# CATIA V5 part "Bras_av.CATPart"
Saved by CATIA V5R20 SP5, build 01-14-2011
Part number: Skl_Bras_av
Publications: "Axe_glissiere_bras_av/vol_av", "Axe_pivot_bras_av/pignon_av", "Plan_glissiere_bras_av/vol_av", "Plan xy"
Bounding box of the stored display mesh (mm): x 0 to 0, y 390 to 430, z -10 to 150
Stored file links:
  U:\2A\CFAO\dossier sans titre\Bras_av.CATPart
  U:\2A\CFAO\dossier sans titre\Skl_gouvernail.CATProduct
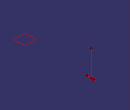
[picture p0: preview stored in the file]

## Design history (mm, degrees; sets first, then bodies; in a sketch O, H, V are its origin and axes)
Set1
  Point1 to Point4: linked copy from another document
  Plane1 "Plan_xy-10mm": linked copy from another document
Body1 (main body)
  Line1 "Axe_glissiere_bras_av/vol_av": type PtPt, FirstPoint Point1, SecondPoint Point2
  Line2 "Axe_pivot_bras_av/pignon_av": type PtPt, FirstPoint Point3, SecondPoint Point4
  Plane2 "Plan_glissiere_bras_av/vol_av": type Offset, RefPlane Plane1, Offset 0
